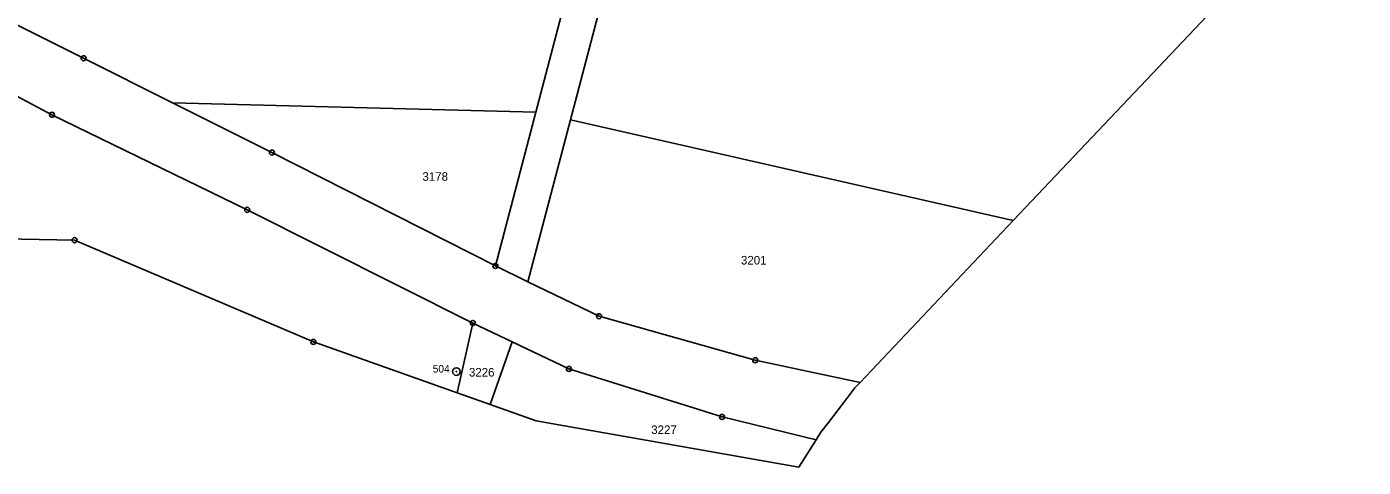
# Model space of a CAD drawing. Extents: x -618848 to -615803, y -1044450 to -1042254.
# Drawn here: x -616614 to -616349.5, y -1043790.3 to -1043703.1 of the extents above; entities that cross this region are included whole.
import ezdxf

# ---------------------------------------------------------------- set-up
doc = ezdxf.new("R2010")
doc.units = 0
doc.header["$LTSCALE"] = 0.68
doc.layers.add('1', color=7, linetype='Continuous', lineweight=25)
doc.layers.add('8', color=7, linetype='Continuous', lineweight=25)
doc.layers.add('2', color=7, linetype='Continuous')

msp = doc.modelspace()

# ---------------------------------------------------------------- linework, layer by layer
at = {"layer": '1'}
for p, q in [((-616506.38, -1043721.5), (-616486.26, -1043644.85)), ((-616513.22, -1043719.99), (-616496.08, -1043654.68)), ((-616418.74, -1043741.47), (-616349.47, -1043668.22)), ((-616602.71, -1043709.3), (-616637.53, -1043691.9)), ((-616638.41, -1043704.95), (-616608.97, -1043720.5)), ((-616585.12, -1043718.12), (-616602.71, -1043709.3)), ((-616513.22, -1043719.99), (-616585.12, -1043718.12)), ((-616585.12, -1043718.12), (-616565.44, -1043727.98)), ((-616608.97, -1043720.5), (-616570.34, -1043739.33)), ((-616521.22, -1043750.45), (-616513.22, -1043719.99)), ((-616514.8, -1043753.56), (-616506.38, -1043721.5)), ((-616506.38, -1043721.5), (-616418.74, -1043741.47)), ((-616565.44, -1043727.98), (-616521.22, -1043750.45)), ((-616570.34, -1043739.33), (-616525.69, -1043761.74)), ((-616449.02, -1043773.49), (-616418.74, -1043741.47)), ((-616618.47, -1043745.04), (-616604.5, -1043745.33)), ((-616604.5, -1043745.33), (-616557.25, -1043765.49)), ((-616514.8, -1043753.56), (-616521.22, -1043750.45)), ((-616500.71, -1043760.39), (-616514.8, -1043753.56)), ((-616525.69, -1043761.74), (-616528.82, -1043775.56)), ((-616517.89, -1043765.47), (-616525.69, -1043761.74)), ((-616469.8, -1043769.11), (-616500.71, -1043760.39)), ((-616557.25, -1043765.49), (-616528.82, -1043775.56)), ((-616522.27, -1043777.88), (-616517.89, -1043765.47)), ((-616517.89, -1043765.47), (-616506.66, -1043770.84)), ((-616449.02, -1043773.49), (-616469.8, -1043769.11)), ((-616506.66, -1043770.84), (-616476.37, -1043780.35)), ((-616451.65, -1043776.66), (-616450.06, -1043774.59)), ((-616450.06, -1043774.59), (-616449.02, -1043773.49)), ((-616528.82, -1043775.56), (-616522.27, -1043777.88)), ((-616455.3, -1043781.42), (-616451.65, -1043776.66)), ((-616522.27, -1043777.88), (-616513.17, -1043781.1)), ((-616476.37, -1043780.35), (-616457.76, -1043784.89)), ((-616513.17, -1043781.1), (-616485.82, -1043785.95)), ((-616456.8, -1043783.38), (-616455.3, -1043781.42)), ((-616461.2, -1043790.31), (-616457.76, -1043784.89)), ((-616457.76, -1043784.89), (-616456.8, -1043783.38)), ((-616485.82, -1043785.95), (-616461.2, -1043790.31))]:
    msp.add_line(p, q, dxfattribs=at)
at = {"layer": '8'}
for centre, radius in [((-616602.71, -1043709.2999), 0.5), ((-616602.71, -1043709.2999), 0.0303), ((-616608.97, -1043720.4999), 0.5), ((-616608.97, -1043720.4999), 0.0303), ((-616565.44, -1043727.9799), 0.5), ((-616565.44, -1043727.9799), 0.0303), ((-616570.34, -1043739.3299), 0.5), ((-616570.34, -1043739.3299), 0.0303), ((-616604.5, -1043745.3299), 0.5), ((-616604.5, -1043745.3299), 0.0303), ((-616521.22, -1043750.4499), 0.5), ((-616521.22, -1043750.4499), 0.0303), ((-616525.69, -1043761.7399), 0.5), ((-616525.69, -1043761.7399), 0.0303), ((-616500.71, -1043760.3899), 0.5), ((-616500.71, -1043760.3899), 0.0303), ((-616557.25, -1043765.4899), 0.5), ((-616557.25, -1043765.4899), 0.0303), ((-616469.8, -1043769.1099), 0.5), ((-616469.8, -1043769.1099), 0.0303), ((-616528.94, -1043771.3598), 0.75), ((-616528.94, -1043771.3598), 0.03), ((-616506.66, -1043770.8399), 0.5), ((-616506.66, -1043770.8399), 0.0303), ((-616476.37, -1043780.3499), 0.5), ((-616476.37, -1043780.3499), 0.0303)]:
    msp.add_circle(centre, radius, dxfattribs=at)

# ---------------------------------------------------------------- texts
at = {"layer": '2'}
for s, p in [('3178', (-616535.66, -1043733.575)), ('3201', (-616472.63, -1043750.155)), ('3226', (-616526.46, -1043772.345)), ('3227', (-616490.38, -1043783.725))]:
    msp.add_text(s, height=1.7, dxfattribs=at).set_placement(p)
at = {"layer": '8'}
msp.add_text('504', height=1.5, dxfattribs=at).set_placement((-616533.62, -1043771.555))

doc.saveas('drawing.dxf')
